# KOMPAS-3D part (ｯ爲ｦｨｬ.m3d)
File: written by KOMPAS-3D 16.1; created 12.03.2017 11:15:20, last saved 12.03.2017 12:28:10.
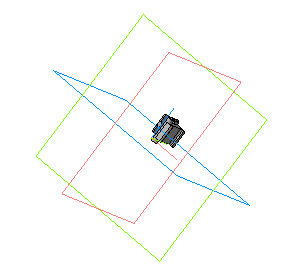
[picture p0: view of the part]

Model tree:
1. Эскиз:1
2. Операция выдавливания:1
     Расстояние 1 = 7
3. Фаска:1
     Угол = 77.4712; Длина 1 = 1; Длина 2 = 4.5
4. Фаска:2
     Угол = 56.3099; Длина 1 = 3; Длина 2 = 4.5
5. Фаска:3
     Угол = 50.1944; Длина 1 = 2.5; Длина 2 = 3
6. Фаска:4
     Угол = 59.0362; Длина 1 = 3; Длина 2 = 5
7. Фаска:5
     Угол = 16.6992; Длина 1 = 5; Длина 2 = 1.5
8. Эскиз:2
9. Операция выдавливания:2
     Расстояние 1 = 1.2
10. Эскиз:3
11. Операция выдавливания:3
     Расстояние 1 = 2
12. Эскиз:4
13. Вырезать элемент выдавливания:1
     Расстояние 1 = 0.75
14. Эскиз:5
15. Вырезать элемент выдавливания:2
     Расстояние 1 = 0.75
16. Эскиз:6
17. Операция выдавливания:4
     Расстояние 1 = 1
18. Скругление:1
     Радиус = 0.5
19. Скругление:2
     Радиус = 0.9
20. Эскиз:7
21. Операция выдавливания:5
     Расстояние 1 = 1.25; Расстояние 2 = 6.75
